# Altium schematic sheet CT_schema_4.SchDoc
size 287 x 163 mm
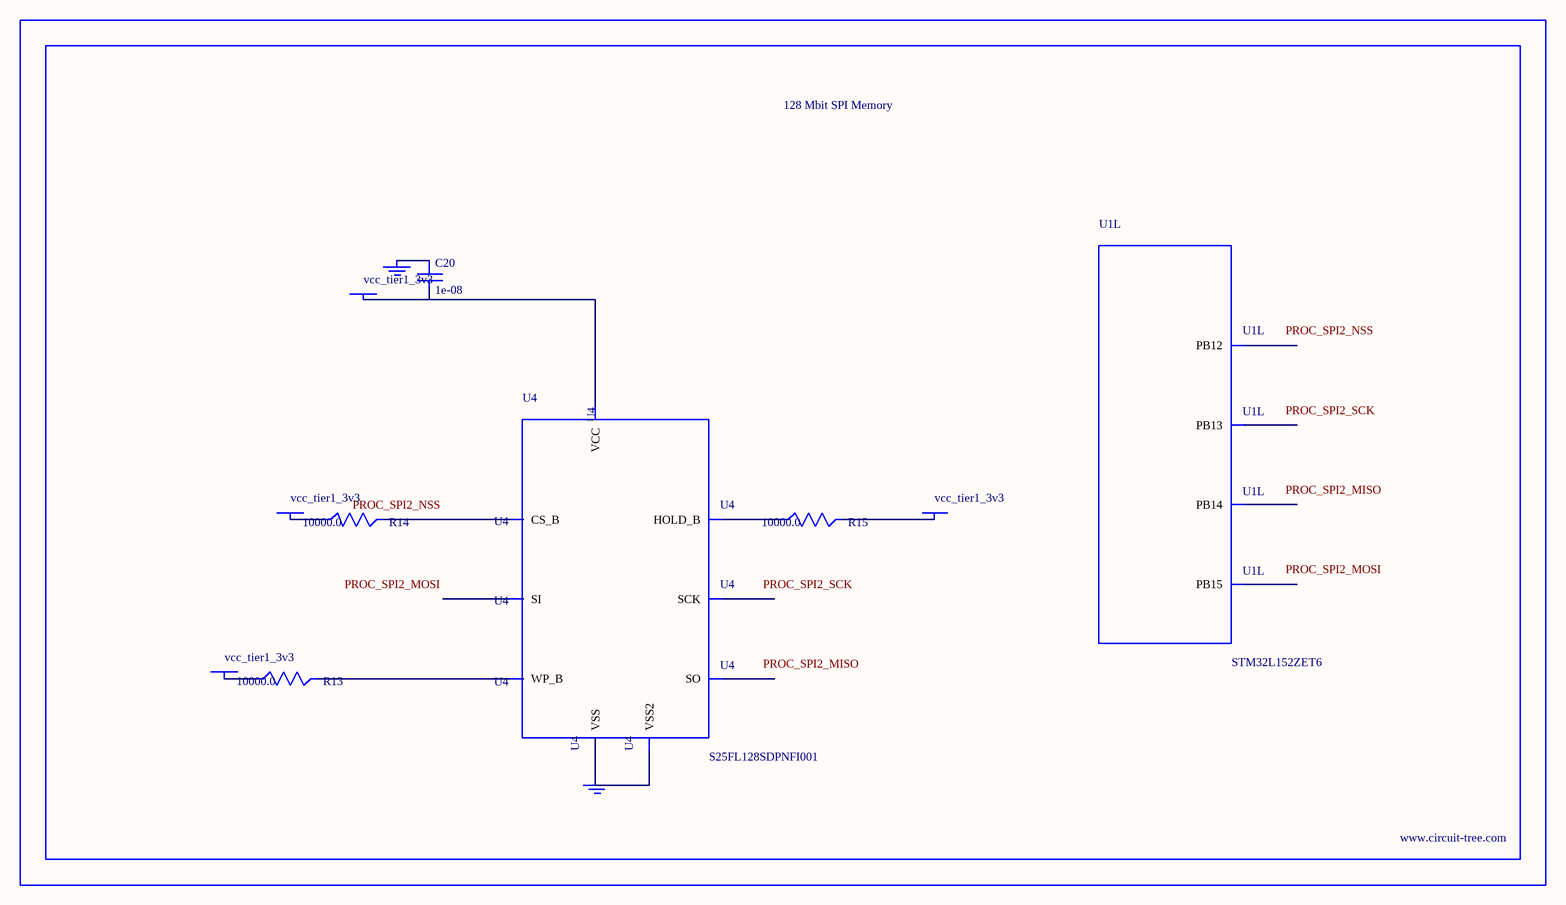
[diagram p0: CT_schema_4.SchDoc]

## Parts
BORDER3  (no value)
C20  1e-08  [C0402]
GND_INSTANCE_3_0  (no value)
GND_INSTANCE_3_1  (no value)
POWER_INSTANCE_3_0  vcc_tier1_3v3
POWER_INSTANCE_3_1  vcc_tier1_3v3
POWER_INSTANCE_3_2  vcc_tier1_3v3
POWER_INSTANCE_3_3  vcc_tier1_3v3
R13  10000.0  [R0603]
R14  10000.0  [R0603]
R15  10000.0  [R0603]
U1  STM32L152ZET6  [LQFP144]  (part L of 13)
U4  S25FL128SDPNFI001  [WNG008]

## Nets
NetC20_1: C20.1 GND_INSTANCE_3_0.0(GND)
NetC20_2: C20.2 POWER_INSTANCE_3_3.0(PWR) U4.8(VCC)
NetGND_INSTANCE_3_1_0: GND_INSTANCE_3_1.0(GND) U4.4(VSS) U4.PAD(VSS2)
NetPOWER_INSTANCE_3_0_0: POWER_INSTANCE_3_0.0(PWR) R14.1
NetPOWER_INSTANCE_3_1_0: POWER_INSTANCE_3_1.0(PWR) R13.1
NetPOWER_INSTANCE_3_2_0: POWER_INSTANCE_3_2.0(PWR) R15.2
NetR13_2: R13.2 U4.3(WP_B)
NetR14_2: R14.2 U4.1(CS_B)
NetR15_1: R15.1 U4.7(HOLD_B)

Not connected (* = marked no-connect by the designer): U1 73(PB12) 74(PB13) 75(PB14) 76(PB15); U4 2(SO) 5(SI) 6(SCK)

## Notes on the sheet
- Labels drawn without touching a wire or pin: PROC_SPI2_MISO, PROC_SPI2_MOSI, PROC_SPI2_NSS, PROC_SPI2_SCK

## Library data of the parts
BORDER3 = BORDER_PAGE3
C20 = C0402C103K3RAC
GND_INSTANCE_3_0 GND_INSTANCE_3_1 = GND
POWER_INSTANCE_3_0-POWER_INSTANCE_3_3 = PWR
R13-R15 = RC0603JR-0710KL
